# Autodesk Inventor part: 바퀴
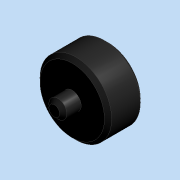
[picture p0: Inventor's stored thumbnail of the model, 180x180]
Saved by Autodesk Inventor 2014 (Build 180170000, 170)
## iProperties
Company: 한국ATC센터
Created: 2015-05
Part Number: 바퀴
Document SubType Name: 모델링
Designer: KYOUNG IL JANG
Vendor: CBT Solutions
Material: 일반
Appearance: 기본값
Author: KYOUNG IL JANG
Comments: 파생
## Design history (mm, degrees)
derived "바퀴.ipt"
node "솔리드1"
node "솔리드 본체"
node "곡면 본체"
feature "솔리드1::바퀴.ipt" dims "d0" = 10
tag "피쳐 태그1"
